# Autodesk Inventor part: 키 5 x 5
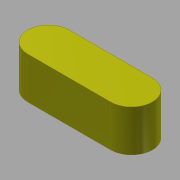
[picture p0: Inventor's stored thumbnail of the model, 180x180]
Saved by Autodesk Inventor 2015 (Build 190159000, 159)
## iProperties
Created: 2011-04
Part Number: 키 5 x 5
Document SubType Name: Modeling
Designer: pww
Density: 7.86 g/cm^3
Material: 강철, 연강
Appearance: 노란색
Author: pww
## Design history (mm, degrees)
sketch "스케치1"
  geometry: L1 (-5, -2.5)-(5, -2.5); L2 (5, 2.5)-(-5, 2.5); A1 r 2.5 centre (-5, 0) between (-5, 2.5) and (-5, -2.5); A2 r 2.5 centre (5, 0) between (5, -2.5) and (5, 2.5); 1 further point
  constraints: 4 end point, 4 point on circle, 2 centre point
extrude "돌출1" new body sketch "스케치1" distance "d0" = 5; taper "d1" = 0 deg
node "솔리드1"
